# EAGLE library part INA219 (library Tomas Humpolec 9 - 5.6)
Zerø-Drift, Bi-Directional CURRENT/POWER MONITOR with I2C Interface FEATURES - SENSES BUS VOLTAGES FROM 0V TO +26V - REPORTS CURRENT, VOLTAGE, AND POWER - 16 PROGRAMMABLE ADDRESSES - HIGH ACCURACY: 1% (Max) OVER TEMPERATURE - FILTERING OPTIONS - CALIBRATION REGISTERS - SOT23-8 AND SO-8 PACKAGES DESCRIPTION The INA219 is a high-side current shunt and power monitor with an I2C interface. The INA219 monitors bproothgramsmhuanbtle dcroonpverasniodn tsimupepsly anvdoltfailgteer,ing.with programmable calibration value, combined with an internal multiplier, enables direct readouts in amperes. An additional multiplying register calculates pproowgerar mimn abwleatatsd.dreTshsees.I2C interface features 16. The INA219 senses across shunts on buses that can vary from 0V to 26V. The device uses a single +3V to +5.5V supply. www.ti.com
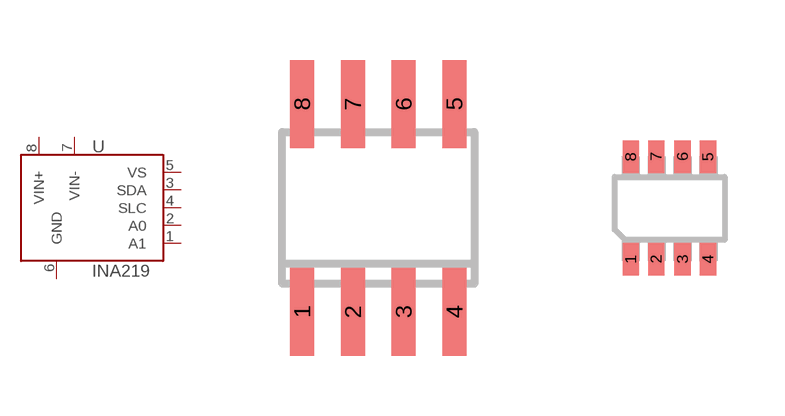
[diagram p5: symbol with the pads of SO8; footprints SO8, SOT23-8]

Designator prefix -

## INA219SO8  [SO8]
1  A1
2  A0
3  SDA
4  SLC
5  VS  pwr
6  GND  pwr
7  VIN-  in
8  VIN+  in

## INA219SOT23-8  [SOT23-8]
1  VIN+  in
2  VIN-  in
3  GND  pwr
4  VS  pwr
5  SLC
6  SDA
7  A0
8  A1

## Footprint SO8 (pad centres in mm)
SMALL OUTLINE INTEGRATED CIRCUIT Body 3.9 mm/JEDEC MS-012AA
smd 0.6 x 2.2: 1 -1.27,-2.6; 2 0,-2.6; 3 1.27,-2.6; 4 2.54,-2.6; 5 2.54,2.6; 6 1.27,2.6; 7 0,2.6; 8 -1.27,2.6

## Footprint SOT23-8 (pad centres in mm)
SOT23-8 Plastic Small-Outline Package
smd 0.406 x 0.813: 1 -2.286,-1.143; 2 -1.651,-1.143; 3 -0.991,-1.143; 4 -0.356,-1.143; 5 -0.356,1.422; 6 -0.991,1.422; 7 -1.651,1.422; 8 -2.286,1.422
